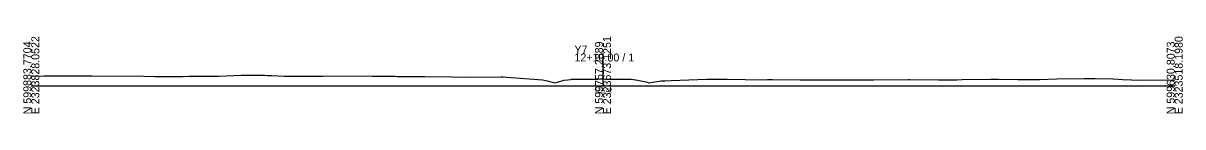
# Model space of a CAD drawing. Extents: x -26 to 3203, y -10 to 1017.
# Drawn here: x 1397.2 to 1802.8, y -9.7 to 17.3 of the extents above; entities that cross this region are included whole.
import ezdxf

# ---------------------------------------------------------------- set-up
doc = ezdxf.new("R2010")
doc.units = 0
for name, color, linetype in [('Default', 7, 'Continuous'), ('Exist CMT Pavement', 7, 'Continuous'), ('Exist Cross Section Cell', 7, 'Continuous'), ('Exist XS Center Line Elevation Label', 7, 'Continuous'), ('Exist XS Ground Line', 7, 'Continuous'), ('Prop XS Earthwork Shape', 7, 'Continuous')]:
    doc.layers.add(name, color=color, linetype=linetype)

msp = doc.modelspace()

# ---------------------------------------------------------------- linework, layer by layer
at = {"layer": 'Exist CMT Pavement'}
msp.add_line((1600, 2.42), (1600, 2.42), dxfattribs=at)
for points in [[(1600, 2.42), (1600, 2.52), (1600.1, 2.52), (1600.1, 2.42)], [(1600, 2.42), (1600, 2.42), (1600, 2.42), (1600, 2.42)]]:
    msp.add_lwpolyline(points, dxfattribs=at)
at = {"layer": 'Exist Cross Section Cell'}
for p, q in [((1600, 0), (1600, 11.38)), ((1400, 0), (1600, 0)), ((1600, 0), (1800, 0))]:
    msp.add_line(p, q, dxfattribs=at)
at = {"layer": 'Exist XS Ground Line'}
msp.add_lwpolyline([(1400, 3.47), (1404.46, 3.5), (1406.44, 3.53), (1414.3, 3.57), (1415.48, 3.57), (1421.12, 3.57), (1439.35, 3.46), (1443.36, 3.35), (1445.71, 3.26), (1452.06, 3.32), (1453.16, 3.34), (1455.27, 3.37), (1455.77, 3.38), (1457.5, 3.38), (1458.69, 3.38), (1459.7, 3.38), (1460.59, 3.38), (1461.4, 3.38), (1462.15, 3.39), (1462.87, 3.39), (1463.57, 3.39), (1464.25, 3.39), (1464.94, 3.4), (1465.64, 3.4), (1473.43, 3.76), (1480.01, 3.79), (1480.66, 3.77), (1481.57, 3.73), (1482.62, 3.69), (1484.17, 3.63), (1486.41, 3.53), (1488.52, 3.44), (1490.17, 3.44), (1493.9, 3.45), (1498.45, 3.46), (1499.86, 3.46), (1500.52, 3.46), (1501.01, 3.47), (1501.95, 3.47), (1502.59, 3.48), (1519.4, 3.42), (1520.13, 3.39), (1520.84, 3.39), (1521.49, 3.38), (1522.08, 3.37), (1522.59, 3.37), (1523.02, 3.36), (1526.5, 3.36), (1527.3, 3.36), (1528.02, 3.35), (1528.67, 3.34), (1535.25, 3.29), (1535.99, 3.28), (1536.63, 3.27), (1537.17, 3.27), (1537.63, 3.26), (1547.12, 3.12), (1552.61, 3.06), (1564.42, 3.2), (1565.1, 3.2), (1566.4, 3.1), (1578.88, 2.14), (1580.5, 1.73), (1583.2, 1.08), (1584.73, 1.58), (1586.42, 1.98), (1588.72, 2.27), (1589.03, 2.31), (1593.16, 2.36), (1598.19, 2.4), (1599.12, 2.43), (1600, 2.42), (1601.59, 2.41), (1609.8, 2.34), (1610.66, 2.25), (1612.06, 2), (1615.52, 1.25), (1616.06, 1.11), (1618.11, 1.42), (1620.42, 1.74), (1621.61, 1.78), (1623.87, 1.89), (1636.18, 2.4), (1643.49, 2.31), (1656.03, 2.18), (1657.5, 2.2), (1659.3, 2.22), (1668.94, 2.18), (1671.72, 2.12), (1675.12, 2.1), (1681.85, 2.12), (1685.93, 2.12), (1690.93, 2.15), (1694.76, 2.16), (1706.75, 2.25), (1707.26, 2.26), (1717.42, 2.09), (1719.44, 2.07), (1723.48, 2.17), (1723.79, 2.17), (1725.61, 2.19), (1735.57, 2.3), (1738.38, 2.3), (1745.08, 2.2), (1752.77, 2.26), (1758.79, 2.44), (1768.27, 2.56), (1771.23, 2.57), (1772.22, 2.59), (1778.34, 2.49), (1781.75, 2.29), (1788.03, 2.03), (1800, 2.13)], dxfattribs=at)
at = {"layer": 'Prop XS Earthwork Shape'}
msp.add_lwpolyline([(1600, 2.42), (1600.1, 2.42), (1600.1, 2.52), (1600, 2.52)], close=True, dxfattribs=at)

# ---------------------------------------------------------------- texts
at = {"layer": 'Default'}
msp.add_text('-', height=0.0001, dxfattribs=at).set_placement((1400, 0))
at = {"layer": 'Exist Cross Section Cell'}
for s, p in [('E 2323828.0522', (1402.8, -10)), ('E 2323673.1251', (1602.8, -10)), ('E 2323518.1980', (1802.8, -10)), ('N 599883.7704', (1400, -10)), ('N 599757.2889', (1600, -10)), ('N 599630.8073', (1800, -10))]:
    msp.add_text(s, height=2.8, rotation=90, dxfattribs=at).set_placement(p)
for s, p in [('Y7', (1590, 11.38)), ('12+10.00 / 1', (1590, 8.58))]:
    msp.add_text(s, height=2.8, dxfattribs=at).set_placement(p)
at = {"layer": 'Exist XS Center Line Elevation Label'}
msp.add_text('122.42', height=1.5, dxfattribs=at).set_placement((1596.94, -2.33))

doc.saveas('drawing.dxf')
